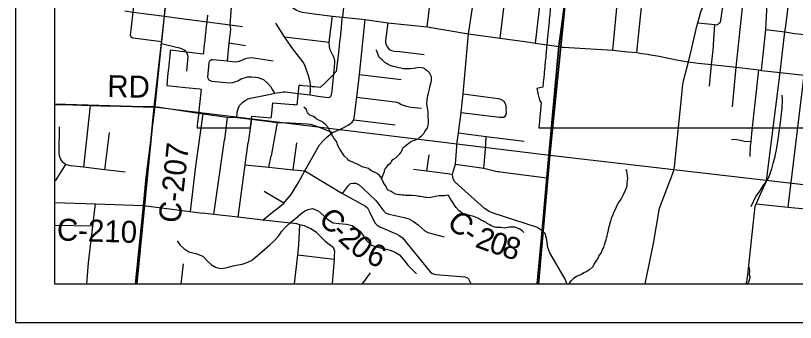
# Model space of a CAD drawing. Extents: x -8.2 to 38.5, y -0.1 to 21.9.
# Drawn here: x 2.063 to 4.076, y 13.864 to 14.657 of the extents above; entities that cross this region are included whole.
import ezdxf

# ---------------------------------------------------------------- set-up
doc = ezdxf.new("R2010")
doc.units = 0
for name, color, linetype in [('Default', 7, 'Continuous'), ('GM_X_Adjacent_County_Text', 7, 'Continuous'), ('GM_X_Airport_Location_Class_2', 7, 'Continuous'), ('GM_X_Minor_Lake', 7, 'Continuous'), ('GM_X_Minor_River', 7, 'Continuous'), ('GM_X_Section', 7, 'Continuous'), ('GM_X_Township', 7, 'Continuous'), ('GM_X_Township_Subdivision_Text', 7, 'Continuous'), ('GM_X_Township_Text', 7, 'Continuous')]:
    doc.layers.add(name, color=color, linetype=linetype)

msp = doc.modelspace()

# ---------------------------------------------------------------- linework, layer by layer
at = {"layer": 'Default'}
for points in [[(3.6725, 16.67), (3.6705, 16.651), (3.6688, 16.6346), (3.6178, 16.1066), (3.5847, 15.7703), (3.5728, 15.6426), (3.5629, 15.5356), (3.5403, 15.2932), (3.5225, 15.0941), (3.5065, 14.9452), (3.4936, 14.7944), (3.4743, 14.647), (3.4653, 14.578), (3.4343, 14.2388), (3.4223, 14.1017), (3.4095, 13.9645), (4.8235, 13.9645)], [(2.1634, 15.4317), (2.1634, 13.9645), (3.4095, 13.9645), (3.4223, 14.1017), (3.4343, 14.2388), (3.4653, 14.578), (3.4743, 14.647), (3.4936, 14.7944)], [(3.4445, 14.6922), (3.4409, 14.651), (3.4406, 14.6485), (3.4403, 14.6449), (3.4403, 14.6446), (3.4399, 14.6411), (3.4354, 14.5937), (3.435, 14.5899), (3.4328, 14.5648), (3.4316, 14.5515), (3.4314, 14.55), (3.431, 14.545), (3.4303, 14.5385), (3.4291, 14.5254), (3.4281, 14.5161), (3.4278, 14.5125), (3.4274, 14.5086), (3.4273, 14.5076), (3.4273, 14.5069), (3.4263, 14.4963), (3.4252, 14.4857), (3.4239, 14.4726), (3.4083, 14.469), (3.4103, 14.4607), (3.4122, 14.4524), (3.4146, 14.4423), (3.4153, 14.4391), (3.4198, 14.4319), (3.4142, 14.3761), (3.4134, 14.3688), (3.4133, 14.3673), (4.8235, 14.3673)], [(2.5586, 14.6586), (2.5575, 14.6492), (2.5574, 14.6478), (2.5573, 14.6473), (2.5565, 14.6398), (2.556, 14.635), (2.5555, 14.6303), (2.5546, 14.6218), (2.5545, 14.6209), (2.5533, 14.6106), (2.5529, 14.6067), (2.5523, 14.6012), (2.5517, 14.5949), (2.5513, 14.5917), (2.5504, 14.5833), (2.5503, 14.5823), (2.5493, 14.5732), (2.5493, 14.5729), (2.5482, 14.563), (2.5481, 14.5621), (2.5476, 14.5574), (2.4626, 14.5681), (2.4622, 14.5636), (2.4596, 14.537), (2.459, 14.5309), (2.4585, 14.5259), (2.4573, 14.5152), (2.4557, 14.4997), (2.4533, 14.477), (2.4698, 14.4751), (2.5015, 14.4718), (2.5386, 14.4679), (2.5424, 14.4675), (2.5381, 14.4278), (2.5363, 14.4109), (2.5353, 14.4015), (2.5343, 14.3921), (2.5332, 14.3826), (2.5322, 14.3732), (2.5316, 14.3673), (2.6694, 14.3673), (2.6704, 14.377), (2.6727, 14.3978), (2.7032, 14.3951), (2.7035, 14.3951), (2.723, 14.3935), (2.7234, 14.3972), (2.7251, 14.4135), (2.7269, 14.432), (2.7582, 14.4293), (2.7798, 14.4275), (2.7836, 14.4272), (2.7897, 14.4267), (2.7951, 14.4778), (2.8003, 14.4773), (2.8048, 14.4768), (2.8269, 14.4746), (2.8289, 14.4744), (2.8337, 14.474), (2.8345, 14.4739), (2.8504, 14.4723), (2.8584, 14.4802), (2.8653, 14.4871), (2.8819, 14.5037), (2.8919, 14.5136), (2.8963, 14.554), (2.8981, 14.5699), (2.9, 14.5892), (2.9023, 14.6068), (2.9028, 14.6109), (2.9032, 14.6154), (2.9064, 14.6494), (2.9065, 14.6506), (2.9072, 14.6502), (2.9076, 14.6538), (2.9113, 14.6859)]]:
    msp.add_lwpolyline(points, dxfattribs=at)
for points in [[(2.1634, 15.4334), (2.1634, 14.4283), (2.4212, 14.4207), (2.5334, 15.4148)], [(2.1634, 14.4283), (2.1634, 13.9645), (2.3763, 13.9645), (2.4212, 14.4207)], [(2.3763, 13.9645), (3.4124, 13.9645), (3.4423, 14.2958), (2.4212, 14.4207)], [(3.4124, 13.9645), (4.3924, 13.9645), (4.4166, 14.1829), (3.4423, 14.2958)]]:
    msp.add_lwpolyline(points, close=True, dxfattribs=at)
at = {"layer": 'GM_X_Adjacent_County_Text'}
for points in [[(2.5334, 15.4148), (3.5428, 15.2954), (3.4423, 14.2958), (2.4212, 14.4207)], [(3.5428, 15.2954), (4.5212, 15.1931), (4.4166, 14.1829), (3.4423, 14.2958)]]:
    msp.add_lwpolyline(points, close=True, dxfattribs=at)
at = {"layer": 'GM_X_Airport_Location_Class_2'}
for p, q in [((2.2558, 14.4249), (2.2382, 14.2658)), ((2.6096, 14.3949), (2.6027, 14.3364)), ((2.6723, 14.3896), (2.6638, 14.3291)), ((2.2935, 14.2588), (2.3053, 14.3554)), ((3.2717, 14.263), (3.2764, 14.3111)), ((3.125, 14.2553), (3.1306, 14.2977)), ((2.1918, 14.2723), (2.1655, 14.2304)), ((3.3476, 14.2492), (3.4345, 14.2383)), ((2.2628, 14.113), (2.1634, 14.1147)), ((2.7915, 14.0393), (2.8855, 14.0278)), ((2.8855, 14.0278), (2.8803, 13.9645)), ((2.4906, 13.9645), (2.4966, 14.016)), ((2.9588, 13.9645), (2.9794, 13.9923))]:
    msp.add_line(p, q, dxfattribs=at)
for points in [[(2.5463, 14.4032), (2.5278, 14.2683), (2.5143, 14.151)], [(2.3465, 14.2526), (2.2935, 14.2588), (2.2382, 14.2658), (2.2052, 14.2687), (2.1918, 14.2723), (2.1863, 14.2778), (2.1824, 14.2822), (2.1796, 14.2869), (2.1768, 14.2945), (2.1757, 14.3036), (2.1769, 14.3701)], [(3.1986, 14.2733), (3.2717, 14.263), (3.3059, 14.2546), (3.3097, 14.2541)], [(3.1908, 14.2465), (3.125, 14.2553), (3.0904, 14.26)], [(3.3097, 14.2541), (3.3466, 14.2493), (3.3476, 14.2492)], [(2.9072, 14.1976), (2.9225, 14.2186), (2.928, 14.2233), (2.9349, 14.2247), (2.9417, 14.2243), (2.9498, 14.2204), (2.9602, 14.2102), (2.9933, 14.1792), (3.0107, 14.1553), (3.0179, 14.1476), (3.0265, 14.1442), (3.0427, 14.141), (3.0665, 14.1356), (3.0781, 14.1317), (3.0902, 14.1256), (3.102, 14.1164), (3.1115, 14.1084), (3.1194, 14.1012), (3.1268, 14.0971), (3.1694, 14.086)], [(2.2472, 13.9645), (2.2519, 14.0188), (2.2628, 14.113), (2.2696, 14.1711)], [(2.8622, 14.0747), (2.8826, 14.0585), (2.8867, 14.0487), (2.8858, 14.0366), (2.8855, 14.0278)], [(2.7835, 13.9645), (2.7915, 14.0393), (2.7942, 14.064)]]:
    msp.add_lwpolyline(points, dxfattribs=at)
at = {"layer": 'GM_X_Minor_River'}
for points in [[(3.0079, 14.2353), (3.0112, 14.2444), (3.0153, 14.2545), (3.0162, 14.2602), (3.0193, 14.2639), (3.0248, 14.2714), (3.0315, 14.2769), (3.0334, 14.2799), (3.037, 14.2851), (3.0447, 14.2899), (3.0514, 14.2962), (3.0549, 14.2999), (3.0581, 14.3044), (3.0597, 14.3081), (3.0625, 14.3145), (3.0672, 14.3186), (3.0746, 14.3249), (3.0789, 14.3289), (3.0824, 14.3311), (3.0862, 14.3329), (3.0897, 14.3343), (3.0939, 14.3357), (3.0997, 14.3382), (3.1027, 14.3397), (3.1078, 14.3437), (3.1109, 14.3463), (3.1168, 14.3522), (3.1196, 14.3575), (3.1251, 14.3657), (3.1268, 14.3706), (3.128, 14.3744), (3.1286, 14.3809), (3.1288, 14.3873), (3.1282, 14.3938), (3.128, 14.3999), (3.1281, 14.4033), (3.1278, 14.4083), (3.1262, 14.4182), (3.1256, 14.4236), (3.125, 14.4293), (3.1252, 14.4392), (3.1274, 14.4506), (3.1291, 14.457), (3.1304, 14.4635), (3.1313, 14.4672), (3.1326, 14.4733), (3.136, 14.485), (3.1369, 14.4907), (3.137, 14.4953), (3.1367, 14.4991), (3.1342, 14.5045), (3.1313, 14.5091), (3.1284, 14.513), (3.1231, 14.5166), (3.1198, 14.5197), (3.1164, 14.521), (3.1119, 14.5222), (3.1066, 14.5232), (3.1005, 14.5226), (3.0959, 14.5215), (3.0902, 14.5206), (3.0818, 14.5197), (3.078, 14.5194), (3.0647, 14.5198), (3.0578, 14.5211), (3.0522, 14.522), (3.0492, 14.5232), (3.0378, 14.5258), (3.0303, 14.5283), (3.0273, 14.5292), (3.022, 14.5324), (3.016, 14.536), (3.009, 14.543), (3.0049, 14.5466), (3.0005, 14.5505), (2.9952, 14.5659), (2.9926, 14.569)], [(4.0404, 14.4516), (4.0413, 14.4401), (4.0408, 14.4166), (4.0389, 14.403), (4.0371, 14.3889), (4.0353, 14.3742), (4.033, 14.3567), (4.0312, 14.3442), (4.0298, 14.3317), (4.028, 14.3211), (4.0259, 14.3113), (4.0237, 14.2984), (4.0216, 14.2886), (4.0179, 14.275), (4.0142, 14.2614), (4.0069, 14.241), (3.9986, 14.2271), (3.992, 14.2174), (3.9833, 14.2039), (3.9739, 14.1904), (3.9668, 14.1758), (3.9604, 14.163)], [(2.8838, 14.342), (2.882, 14.3458), (2.8776, 14.3528), (2.8754, 14.3571), (2.8736, 14.3613), (2.8704, 14.3683), (2.863, 14.3757), (2.8589, 14.3792), (2.8552, 14.3831), (2.8492, 14.3856), (2.8417, 14.3892), (2.838, 14.392), (2.8324, 14.3964), (2.8226, 14.4001), (2.8193, 14.4036), (2.8167, 14.4071), (2.8153, 14.4105), (2.8139, 14.4144), (2.8076, 14.4207)], [(3.3749, 14.0971), (3.3712, 14.1003), (3.3679, 14.103), (3.3645, 14.105), (3.3585, 14.1078), (3.3547, 14.1095), (3.3513, 14.1103), (3.3479, 14.1108), (3.3422, 14.1106), (3.3369, 14.1104), (3.3246, 14.1084), (3.3205, 14.1085), (3.3144, 14.1095), (3.3038, 14.1098), (3.3007, 14.1102), (3.2977, 14.1114), (3.2947, 14.1127), (3.2906, 14.1143), (3.2872, 14.1163), (3.2835, 14.1183), (3.2805, 14.1203), (3.2768, 14.1231), (3.273, 14.1243), (3.2692, 14.1267), (3.2647, 14.1287), (3.2606, 14.1315), (3.2576, 14.1331), (3.2535, 14.1351), (3.2505, 14.1364), (3.246, 14.138), (3.2346, 14.141), (3.2312, 14.1419), (3.2275, 14.1431), (3.2203, 14.1441), (3.2165, 14.1461), (3.2113, 14.1504), (3.2084, 14.1532), (3.2006, 14.161), (3.1958, 14.1676), (3.1842, 14.1862), (3.1809, 14.192), (3.1771, 14.1929), (3.1737, 14.1926), (3.1699, 14.1919), (3.16, 14.1918), (3.1565, 14.1915), (3.1508, 14.1909), (3.1439, 14.1892), (3.1382, 14.1879), (3.1351, 14.1876), (3.1283, 14.1866), (3.1245, 14.1871), (3.1214, 14.1876), (3.1082, 14.1895), (3.1044, 14.1896), (3.1002, 14.1905), (3.0972, 14.1913), (3.0866, 14.1924), (3.0794, 14.1926), (3.0699, 14.1924), (3.0664, 14.1929), (3.0611, 14.1934), (3.057, 14.1939), (3.0539, 14.194), (3.0482, 14.1946), (3.0441, 14.1958), (3.0381, 14.1994), (3.0329, 14.203), (3.025, 14.2066), (3.022, 14.209), (3.0206, 14.2132), (3.0184, 14.2171), (3.014, 14.2237), (3.0122, 14.2276), (3.0101, 14.2322), (3.0079, 14.2353), (3.0076, 14.2384), (3.0028, 14.2442), (2.9961, 14.2493), (2.9927, 14.2506), (2.9803, 14.257), (2.974, 14.2621), (2.96, 14.266), (2.9555, 14.2684), (2.9465, 14.2724), (2.9409, 14.2749), (2.9371, 14.2769), (2.9323, 14.2797), (2.9243, 14.2818), (2.921, 14.2842), (2.9195, 14.2873), (2.9121, 14.2943), (2.9099, 14.2975), (2.9074, 14.3021), (2.9001, 14.3122), (2.8968, 14.3184), (2.8943, 14.3242), (2.8929, 14.3273), (2.8911, 14.3323), (2.8885, 14.3358), (2.8838, 14.342)], [(3.4919, 13.9645), (3.4946, 13.9681), (3.4978, 13.973), (3.5045, 13.9796), (3.511, 13.9836), (3.516, 13.9858), (3.5241, 13.9894), (3.5295, 13.9934), (3.5365, 13.9959), (3.5411, 13.9995), (3.5458, 14.0021), (3.5536, 14.0091), (3.5567, 14.0147), (3.5615, 14.023), (3.5671, 14.0304), (3.5687, 14.0357), (3.5755, 14.0454), (3.5779, 14.053), (3.5811, 14.0582), (3.5832, 14.0646), (3.5861, 14.0737), (3.5874, 14.0782), (3.5886, 14.0832), (3.5899, 14.0877), (3.5912, 14.0926), (3.5921, 14.0972), (3.5934, 14.1032), (3.5947, 14.1089), (3.5956, 14.115), (3.5985, 14.1244), (3.6002, 14.1297), (3.6019, 14.1365), (3.6051, 14.1425), (3.6063, 14.147), (3.6096, 14.1538), (3.614, 14.1628), (3.6188, 14.1722), (3.6228, 14.1778), (3.6263, 14.183), (3.6299, 14.1894), (3.6324, 14.1947), (3.6372, 14.206), (3.64, 14.212), (3.6414, 14.218), (3.6419, 14.2249), (3.6428, 14.2306), (3.643, 14.237), (3.6428, 14.242), (3.6414, 14.2489), (3.6405, 14.255), (3.6394, 14.2596)], [(2.4803, 14.0753), (2.4876, 14.0649), (2.4973, 14.0552), (2.5108, 14.0469), (2.5205, 14.0441), (2.5315, 14.0419), (2.5462, 14.0359), (2.5584, 14.0227), (2.5688, 14.013), (2.5789, 14.0075), (2.5913, 14.0038), (2.6058, 14.0058), (2.6245, 14.0107), (2.6378, 14.0131), (2.6477, 14.0148), (2.6584, 14.0183), (2.6722, 14.0241), (2.6826, 14.0334), (2.6934, 14.0426), (2.7062, 14.0534), (2.7194, 14.0653), (2.7298, 14.0742), (2.7415, 14.0872), (2.7508, 14.0999), (2.7602, 14.1104), (2.7737, 14.1234), (2.7853, 14.133), (2.7993, 14.1452), (2.8093, 14.1523), (2.8188, 14.1566), (2.8299, 14.159), (2.8442, 14.153), (2.8587, 14.1398), (2.8694, 14.1301), (2.8829, 14.1222), (2.8973, 14.12), (2.9177, 14.118), (2.9317, 14.1147), (2.9418, 14.1084), (2.9514, 14.1002), (2.9599, 14.0894), (2.9687, 14.0759), (2.9821, 14.0642), (2.9919, 14.061), (3.0051, 14.0576), (3.0194, 14.0535), (3.033, 14.0506), (3.0431, 14.0458), (3.054, 14.0395), (3.0636, 14.0279), (3.0754, 14.0124), (3.0876, 14.0004), (3.098, 13.9899)], [(3.9532, 13.9645), (3.9532, 13.9645), (3.9552, 13.9697), (3.9584, 13.9773), (3.9586, 13.9815), (3.9576, 13.9876), (3.9579, 13.9975), (3.9576, 14.0021), (3.957, 14.0063)]]:
    msp.add_lwpolyline(points, dxfattribs=at)
at = {"layer": 'GM_X_Section'}
msp.add_lwpolyline([(2.1634, 20.7645), (2.1634, 13.9645), (4.8235, 13.9645)], dxfattribs=at)
at = {"layer": 'GM_X_Township'}
for p, q in [((2.0634, 20.8645), (2.0634, 13.8645)), ((2.1634, 20.7645), (2.1634, 13.9645)), ((2.1634, 13.9645), (8.9634, 13.9645)), ((2.1634, 13.9645), (2.1634, 13.9645)), ((2.0634, 13.8645), (9.0634, 13.8645))]:
    msp.add_line(p, q, dxfattribs=at)
at = {"layer": 'GM_X_Township_Subdivision_Text'}
for p, q in [((3.3141, 14.5989), (3.3401, 14.8102)), ((3.4051, 14.5862), (3.4296, 14.8014)), ((2.7574, 14.6021), (2.8728, 14.5882)), ((2.6145, 14.5865), (2.6564, 14.5804)), ((2.9505, 14.5051), (3.0583, 14.4925)), ((2.9359, 14.3878), (3.0425, 14.375)), ((2.5748, 14.1435), (2.6027, 14.3364)), ((2.7796, 14.2591), (2.7893, 14.3283)), ((3.2764, 14.3111), (3.2781, 14.3448)), ((2.7171, 14.2656), (2.7231, 14.295)), ((2.7554, 14.173), (2.7051, 14.2025)), ((2.7942, 14.064), (2.797, 14.1168))]:
    msp.add_line(p, q, dxfattribs=at)
for points in [[(3.1258, 14.6283), (3.1364, 14.7204), (3.146, 14.7957), (3.1627, 14.9716), (3.1664, 14.9968), (3.1756, 15.106)], [(3.9132, 14.4215), (3.9229, 14.5238), (3.9443, 14.7273), (3.9549, 14.8325), (3.9597, 14.8807), (3.9646, 14.9273), (3.9708, 14.9837), (3.9786, 15.0615)], [(4.0573, 14.1626), (4.0984, 14.5037), (4.1001, 14.5204), (4.1098, 14.6072), (4.1178, 14.6816), (4.1244, 14.7511), (4.1327, 14.8141), (4.1553, 15.0436)], [(2.6098, 14.5407), (2.6145, 14.5865), (2.6187, 14.6215), (2.6171, 14.6338), (2.6251, 14.7378), (2.6252, 14.7388), (2.635, 14.8102), (2.6414, 14.8954), (2.6458, 14.9385)], [(3.6664, 14.5615), (3.677, 14.6619), (3.6818, 14.7141), (3.6872, 14.7749), (3.6936, 14.8399)], [(3.6883, 13.9645), (3.7093, 14.0685), (3.7248, 14.1598), (3.7609, 14.2545), (3.7638, 14.2665), (3.7836, 14.4615), (3.7847, 14.4733), (3.7867, 14.4884), (3.7997, 14.5378), (3.8072, 14.5697), (3.8217, 14.63), (3.8238, 14.6389), (3.828, 14.6539), (3.8316, 14.6666), (3.8365, 14.6792), (3.8428, 14.6919), (3.8471, 14.7004), (3.8471, 14.7133), (3.8469, 14.7378), (3.8497, 14.8437)], [(3.9881, 14.5156), (3.9993, 14.6209), (4.0032, 14.6889), (4.013, 14.7676), (4.0223, 14.8251)], [(3.4655, 14.5775), (3.4745, 14.6465), (3.4938, 14.7939)], [(2.4404, 14.5895), (2.3662, 14.5989), (2.3615, 14.6017), (2.3598, 14.6064), (2.3613, 14.6201), (2.3671, 14.6663), (2.3768, 14.768)], [(3.8763, 14.6351), (3.878, 14.6364), (3.8803, 14.6383), (3.8822, 14.6406), (3.8834, 14.6448), (3.8925, 14.7124), (3.8932, 14.7205), (3.894, 14.7281), (3.8952, 14.7313)], [(2.3452, 14.6692), (2.3671, 14.6663), (2.4479, 14.6559), (2.4911, 14.6501), (2.6171, 14.6338), (2.6485, 14.6289)], [(2.8778, 14.4496), (2.8789, 14.4534), (2.8797, 14.458), (2.8801, 14.4626), (2.8865, 14.5243), (2.8873, 14.5362), (2.887, 14.541), (2.8862, 14.5448), (2.8841, 14.5518), (2.875, 14.5687), (2.8731, 14.5769), (2.8728, 14.5882), (2.8816, 14.6561)], [(2.7017, 14.1288), (2.7222, 14.1457), (2.7491, 14.1668), (2.7554, 14.173), (2.7593, 14.1767), (2.7747, 14.1948), (2.794, 14.2276), (2.81, 14.2559), (2.848, 14.3233), (2.8575, 14.334), (2.8663, 14.3434), (2.8814, 14.3556), (2.8882, 14.3574), (2.9068, 14.3668), (2.9215, 14.3745), (2.928, 14.3783), (2.9317, 14.3815), (2.9359, 14.3878), (2.9382, 14.3987), (2.9437, 14.4464), (2.9505, 14.5051), (2.9659, 14.6472)], [(2.8233, 14.4524), (2.8245, 14.4686), (2.8244, 14.4796), (2.8237, 14.4859), (2.8193, 14.5012), (2.8099, 14.5295), (2.8057, 14.5365), (2.7998, 14.5448), (2.7816, 14.5682), (2.7722, 14.5809), (2.7574, 14.6021), (2.7351, 14.6375)], [(3.0244, 14.6387), (3.018, 14.5932), (3.0183, 14.5875), (3.0195, 14.5814), (3.0229, 14.5757), (3.0278, 14.5698), (3.0337, 14.5674), (3.0402, 14.5656), (3.0551, 14.5642), (3.1175, 14.5567)], [(3.8238, 14.6389), (3.8678, 14.6342), (3.8729, 14.6336), (3.874, 14.6339), (3.8746, 14.6342), (3.8763, 14.6351)], [(3.8539, 14.4752), (3.8595, 14.5306), (3.8636, 14.5682), (3.8678, 14.6342)], [(3.9993, 14.6209), (4.0487, 14.615), (4.0586, 14.6136)], [(4.0586, 14.6136), (4.0736, 14.6114), (4.1098, 14.6072), (4.2008, 14.5957), (4.2683, 14.5887), (4.3292, 14.5824), (4.388, 14.5763), (4.3888, 14.5762), (4.4529, 14.5695), (4.5104, 14.5625), (4.567, 14.5556), (4.6241, 14.5486), (4.6666, 14.5434), (4.6697, 14.5426), (4.671, 14.5419), (4.6726, 14.5409)], [(2.5056, 14.5133), (2.5089, 14.5514), (2.5074, 14.5568), (2.5049, 14.5615), (2.5016, 14.5653), (2.4983, 14.5683), (2.4928, 14.5712), (2.4868, 14.573), (2.4789, 14.5752), (2.4399, 14.5846)], [(2.5602, 14.4945), (2.5594, 14.4978), (2.5626, 14.5348), (2.5637, 14.5385), (2.5648, 14.5402), (2.5664, 14.5421), (2.5687, 14.5435), (2.5711, 14.5442), (2.6098, 14.5407), (2.6303, 14.5382), (2.6361, 14.5386), (2.6416, 14.5396), (2.6532, 14.5447), (2.6594, 14.5471), (2.6649, 14.5483), (2.6722, 14.5486), (2.728, 14.5404)], [(3.9588, 14.2935), (3.9595, 14.3208), (3.9613, 14.3321), (3.9633, 14.3526), (3.9811, 14.5167)], [(2.5602, 14.4945), (2.5624, 14.4916), (2.5657, 14.4892), (2.57, 14.4881), (2.6148, 14.4833), (2.6236, 14.4845), (2.6292, 14.486), (2.6367, 14.489), (2.6455, 14.4937), (2.651, 14.4959), (2.6564, 14.4975), (2.6626, 14.4988), (2.6725, 14.4994), (2.6821, 14.4983), (2.6895, 14.4969), (2.7027, 14.4918), (2.7125, 14.4837), (2.7217, 14.4728), (2.7272, 14.4635), (2.7314, 14.457)], [(2.6339, 14.3942), (2.6354, 14.4078), (2.6365, 14.4134), (2.6384, 14.4188), (2.641, 14.4252), (2.6485, 14.4326), (2.656, 14.4381), (2.6636, 14.4418), (2.6695, 14.444), (2.721, 14.4542), (2.7314, 14.457), (2.7446, 14.4588), (2.7543, 14.46), (2.7599, 14.46), (2.7789, 14.4575), (2.8233, 14.4524), (2.8436, 14.4495), (2.8644, 14.4463), (2.8705, 14.4455), (2.8747, 14.4464), (2.8778, 14.4496)], [(3.218, 14.4549), (3.3084, 14.4433), (3.315, 14.4414), (3.3198, 14.4391), (3.3236, 14.4357), (3.3262, 14.4317), (3.328, 14.4274), (3.3296, 14.4161)], [(2.9437, 14.4464), (3.0418, 14.4341), (3.0473, 14.4333), (3.0521, 14.4317), (3.0582, 14.4277), (3.069, 14.4237), (3.0834, 14.4205), (3.1109, 14.4177)], [(3.2128, 14.4071), (3.3124, 14.3947), (3.3154, 14.3944), (3.3196, 14.3944), (3.3236, 14.3952), (3.3268, 14.3978), (3.3294, 14.4017), (3.3302, 14.4062), (3.3296, 14.4161)], [(3.2061, 14.3542), (3.2781, 14.3448), (3.3762, 14.3324)], [(2.6375, 14.1363), (2.656, 14.272), (2.6638, 14.3291)], [(3.9105, 14.3375), (3.9196, 14.3379), (3.9335, 14.3351), (3.9433, 14.3329), (3.9613, 14.3321)], [(2.656, 14.272), (2.7171, 14.2656), (2.7796, 14.2591), (2.81, 14.2559), (2.8964, 14.2035)], [(3.9746, 14.1712), (4.0573, 14.1626), (4.1012, 14.158), (4.106, 14.1575), (4.1417, 14.1538), (4.1464, 14.1533), (4.1513, 14.1528)], [(2.8622, 14.0747), (2.8398, 14.0966), (2.8257, 14.1062), (2.8085, 14.114), (2.797, 14.1168), (2.7889, 14.1188), (2.7017, 14.1288), (2.6375, 14.1363), (2.5748, 14.1435), (2.5461, 14.1468)]]:
    msp.add_lwpolyline(points, dxfattribs=at)
at = {"layer": 'GM_X_Township_Text'}
for p, q in [((3.6042, 14.5677), (3.6289, 14.8236)), ((2.7385, 14.3814), (2.7231, 14.295))]:
    msp.add_line(p, q, dxfattribs=at)
for points in [[(3.2024, 14.3243), (3.2061, 14.3542), (3.2128, 14.4071), (3.218, 14.4549), (3.2325, 14.6103), (3.2465, 14.7062), (3.2551, 14.7824), (3.2599, 14.819), (3.2629, 14.854), (3.2659, 14.8817), (3.274, 14.9861), (3.2879, 15.1173)], [(4.05, 14.6249), (4.0525, 14.6438), (4.0741, 14.8219)], [(2.4239, 14.4222), (2.4399, 14.5846), (2.4404, 14.5895), (2.4479, 14.6559), (2.4557, 14.7598)], [(2.4557, 14.7598), (2.4898, 14.7554), (2.6251, 14.7378), (2.701, 14.7279), (2.707, 14.7259), (2.7148, 14.7223), (2.7884, 14.6713), (2.797, 14.6677), (2.8032, 14.6661), (2.8157, 14.664), (2.8335, 14.6619), (2.8816, 14.6561), (2.9659, 14.6472), (3.0244, 14.6387), (3.1258, 14.6283), (3.2325, 14.6103), (3.3141, 14.5989), (3.3834, 14.5893), (3.4051, 14.5862), (3.4655, 14.5775), (3.475, 14.5761)], [(3.9487, 13.9645), (3.9488, 13.9647), (3.9503, 13.9691), (3.9527, 13.9876), (3.9718, 14.1646), (3.9746, 14.1712), (3.9758, 14.1739), (3.9815, 14.1867), (3.9979, 14.2223), (4.0008, 14.2283), (4.0021, 14.237), (4.0361, 14.5104), (4.0487, 14.615), (4.05, 14.6249)], [(3.475, 14.5761), (3.4769, 14.5758), (3.6042, 14.5677), (3.6437, 14.5634), (3.6664, 14.5615), (3.6785, 14.5597), (3.6949, 14.5573)], [(3.6949, 14.5573), (3.6978, 14.5569), (3.7242, 14.5522), (3.7691, 14.5428), (3.7997, 14.5378), (3.8245, 14.5345), (3.8595, 14.5306), (3.9229, 14.5238), (3.9811, 14.5167), (3.9881, 14.5156), (4.0361, 14.5104), (4.0984, 14.5037), (4.1775, 14.4929)], [(2.1634, 14.4274), (2.2118, 14.4263), (2.2558, 14.4249), (2.2833, 14.4245), (2.4239, 14.4222)], [(2.3725, 13.9645), (2.3931, 14.1668), (2.4005, 14.2394), (2.4073, 14.2931), (2.4239, 14.4222)], [(2.4239, 14.4222), (2.5463, 14.4032), (2.6096, 14.3949), (2.6339, 14.3942), (2.6723, 14.3896), (2.7385, 14.3814), (2.769, 14.38), (2.7723, 14.3799)], [(2.7723, 14.3799), (2.8011, 14.3787), (2.8159, 14.3776), (2.8234, 14.3768), (2.8332, 14.3742), (2.8497, 14.3682), (2.8814, 14.3556)], [(3.1927, 14.2532), (3.1986, 14.2733), (3.2018, 14.3193), (3.2024, 14.3243)], [(3.4119, 14.1084), (3.4103, 14.1096), (3.2954, 14.1471), (3.2857, 14.1512), (3.2734, 14.1591), (3.1973, 14.2274), (3.1922, 14.2359), (3.1918, 14.2402), (3.1908, 14.2465), (3.1927, 14.2532)], [(2.8964, 14.2035), (2.9072, 14.1976), (2.9665, 14.1649), (2.9713, 14.1602), (2.9767, 14.1502), (2.9904, 14.1222), (2.9955, 14.1163), (3.0033, 14.1116), (3.0471, 14.0926), (3.0535, 14.089), (3.0616, 14.0831), (3.1331, 13.9948), (3.1383, 13.9912), (3.1481, 13.9883), (3.2225, 13.9822), (3.2266, 13.9809), (3.2292, 13.9793), (3.2322, 13.9767), (3.234, 13.9739), (3.2385, 13.9645)], [(2.1634, 14.1747), (2.2696, 14.1711), (2.3931, 14.1668), (2.5143, 14.151), (2.5461, 14.1468)], [(3.4865, 13.9645), (3.4863, 13.9653), (3.4817, 13.9761), (3.4419, 14.0439), (3.437, 14.0584), (3.4341, 14.0775), (3.43, 14.0946), (3.4225, 14.1011), (3.4119, 14.1084)]]:
    msp.add_lwpolyline(points, dxfattribs=at)

# ---------------------------------------------------------------- texts
at = {"layer": 'GM_X_Minor_Lake'}
for s, height, rotation, p in [('RD', 0.05682, 359.0128, (2.2996, 14.4467)), ('C-207', 0.05682, 83.8103, (2.4883, 14.1195)), ('C', 0.0568, 316.4366, (2.842, 14.1262)), ('C', 0.0568, 317.736, (3.1731, 14.1176)), ('C-210', 0.05682, 358.0725, (2.1692, 14.0765)), ('-', 0.0568, 316.5426, (2.8759, 14.0939)), ('2', 0.0568, 316.9809, (2.8932, 14.0775)), ('2', 0.0568, 339.5626, (3.2468, 14.0605)), ('0', 0.0568, 321.933, (2.9229, 14.0502)), ('-', 0.0568, 324.7042, (3.2135, 14.0815)), ('0', 0.0568, 341.9873, (3.282, 14.0474)), ('8', 0.0568, 342.1298, (3.3155, 14.0366)), ('6', 0.0568, 337.3396, (2.9648, 14.0202))]:
    msp.add_text(s, height=height, rotation=rotation, dxfattribs=at).set_placement(p)

doc.saveas('drawing.dxf')
